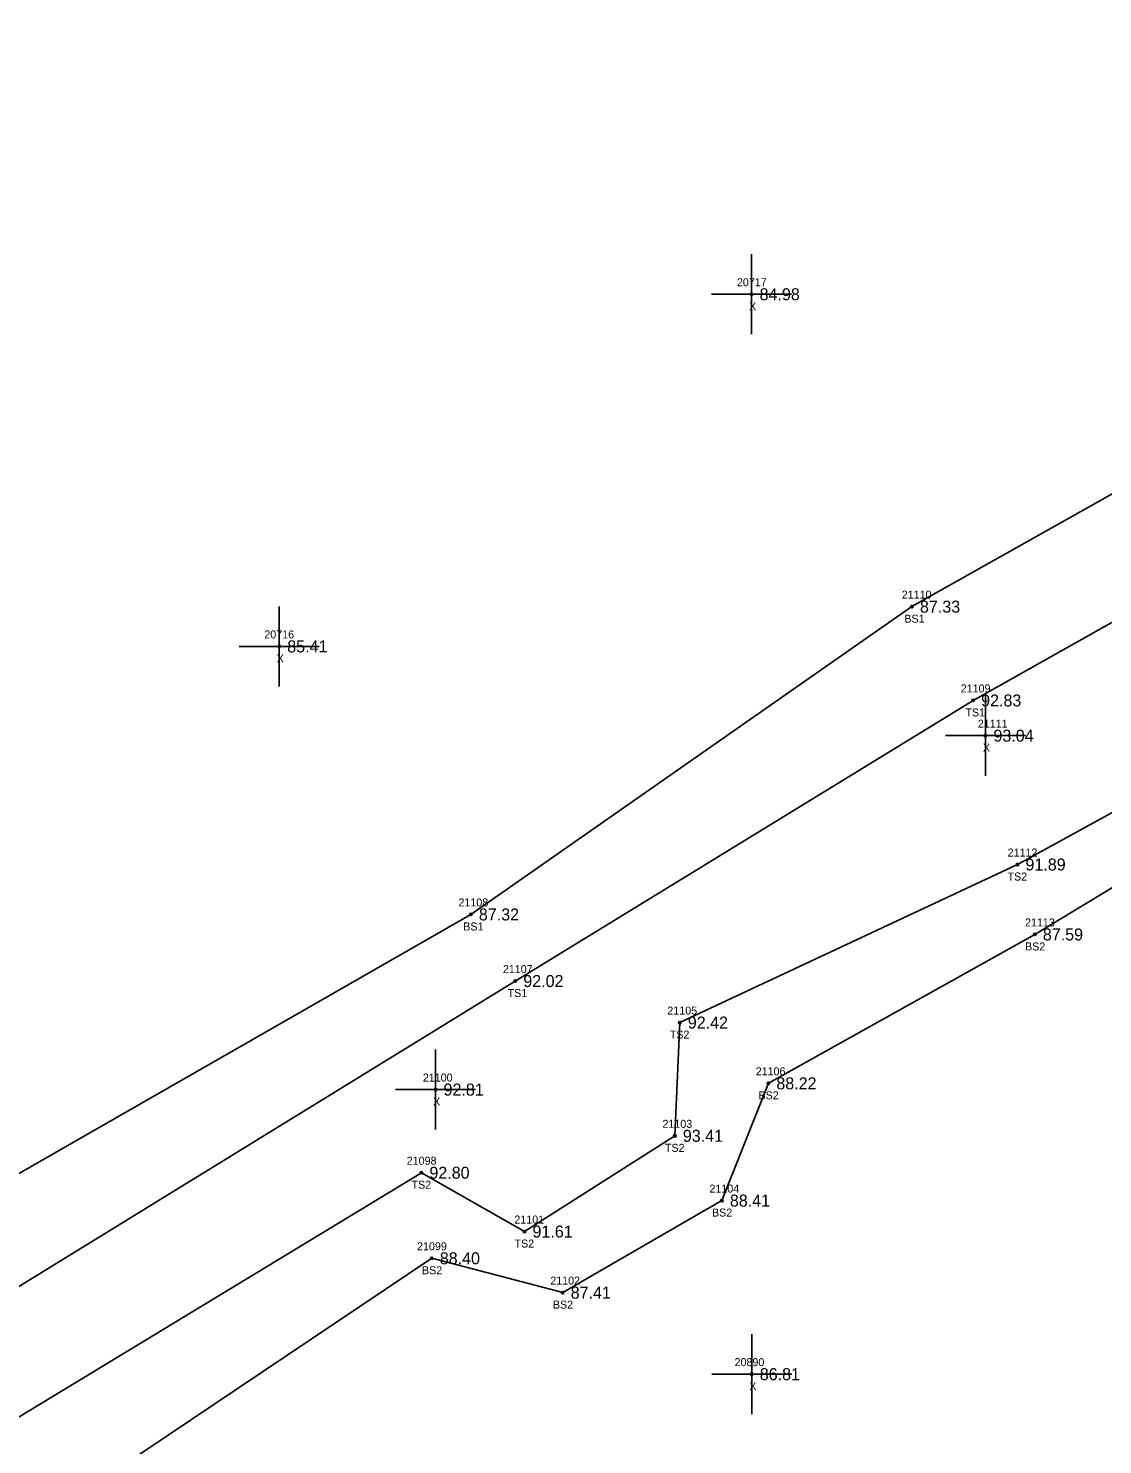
# Model space of a CAD drawing. Extents: x 2530197 to 2532051, y 935230 to 936631.
# Drawn here: x 2531258.3 to 2531392.5, y 936167.6 to 936344.6 of the extents above; entities that cross this region are included whole.
import ezdxf

# ---------------------------------------------------------------- set-up
doc = ezdxf.new("R2010")
doc.units = 0
for name, color, linetype in [('RD_DTM_BkLn2', 7, 'Continuous'), ('RD_DTM_BkLn_txCode', 7, 'Continuous'), ('RD_EX_Misc', 7, 'Continuous'), ('RD_EX_Misc_txCode', 7, 'Continuous'), ('RD_EX_TX_Misc_ELEV', 7, 'Continuous'), ('RD_SMD_Locator', 7, 'Continuous')]:
    doc.layers.add(name, color=color, linetype=linetype)

msp = doc.modelspace()

# ---------------------------------------------------------------- linework, layer by layer
at = {"layer": 'RD_DTM_BkLn2'}
for points in [[(2531151.41, 935999.3), (2531167.24, 936008.08), (2531181.24, 936018.79), (2531181.58, 936027.3), (2531178.12, 936073.45), (2531167.63, 936105.68), (2531166.35, 936111.09), (2531158.41, 936111.85), (2531152.62, 936122.31), (2531150.51, 936125.78), (2531152.42, 936137.74), (2531230.98, 936186.53), (2531313.57, 936233.84), (2531368.67, 936272.3), (2531431.6, 936307.72), (2531489.09, 936344.56)], [(2531153.52, 936135.49), (2531238.65, 936176.03), (2531319.12, 936225.52), (2531376.31, 936260.58), (2531439.07, 936295.88), (2531496.33, 936332.58)], [(2531229.61, 936049.23), (2531205.83, 936108.6), (2531204.82, 936125.4), (2531213.43, 936143.32), (2531245.76, 936164.18), (2531307.39, 936201.57), (2531320.27, 936194.22), (2531339.05, 936206.18), (2531339.67, 936220.33), (2531381.85, 936240.08), (2531451.4, 936278.23)], [(2531232.8, 936067.46), (2531215.52, 936108.97), (2531226.2, 936132.67), (2531251.54, 936152.54), (2531308.69, 936190.88), (2531325.04, 936186.59), (2531344.92, 936198.09), (2531350.73, 936212.74), (2531384.02, 936231.34), (2531448.45, 936270.32)]]:
    msp.add_lwpolyline(points, dxfattribs=at)
at = {"layer": 'RD_EX_Misc'}
for p, q in [((2531348.64, 936306.33), (2531348.64, 936316.33)), ((2531343.64, 936311.33), (2531353.64, 936311.33)), ((2531289.63, 936262.33), (2531289.63, 936272.33)), ((2531284.63, 936267.33), (2531294.63, 936267.33)), ((2531377.85, 936251.18), (2531377.85, 936261.18)), ((2531372.85, 936256.18), (2531382.85, 936256.18)), ((2531309.16, 936206.96), (2531309.16, 936216.96)), ((2531304.16, 936211.96), (2531314.16, 936211.96)), ((2531348.66, 936171.4), (2531348.66, 936181.4)), ((2531343.66, 936176.4), (2531353.66, 936176.4))]:
    msp.add_line(p, q, dxfattribs=at)
at = {"layer": 'RD_SMD_Locator'}
for centre in [(2531348.64, 936311.33), (2531368.67, 936272.3), (2531289.63, 936267.33), (2531376.31, 936260.58), (2531377.85, 936256.18), (2531381.85, 936240.08), (2531313.57, 936233.84), (2531384.02, 936231.34), (2531319.12, 936225.52), (2531339.67, 936220.33), (2531350.73, 936212.74), (2531309.16, 936211.96), (2531339.05, 936206.18), (2531307.39, 936201.57), (2531344.92, 936198.09), (2531320.27, 936194.22), (2531308.69, 936190.88), (2531325.04, 936186.59), (2531348.66, 936176.4)]:
    msp.add_circle(centre, 0.15, dxfattribs=at)

# ---------------------------------------------------------------- texts
at = {"layer": 'RD_DTM_BkLn_txCode'}
for s, p in [('21110', (2531367.4, 936273.3)), ('BS1', (2531367.72, 936270.3)), ('21109', (2531374.76, 936261.58)), ('TS1', (2531375.35, 936258.58)), ('21112', (2531380.62, 936241.08)), ('TS2', (2531380.61, 936238.08)), ('21108', (2531312.02, 936234.84)), ('BS1', (2531312.62, 936231.84)), ('21113', (2531382.79, 936232.34)), ('BS2', (2531382.79, 936229.34)), ('21107', (2531317.57, 936226.52)), ('TS1', (2531318.16, 936223.52)), ('21105', (2531338.11, 936221.33)), ('TS2', (2531338.42, 936218.33)), ('21106', (2531349.15, 936213.74)), ('BS2', (2531349.5, 936210.74)), ('21103', (2531337.5, 936207.18)), ('TS2', (2531337.81, 936204.18)), ('21098', (2531305.56, 936202.57)), ('TS2', (2531306.15, 936199.57)), ('21104', (2531343.37, 936199.09)), ('BS2', (2531343.69, 936196.09)), ('21101', (2531319, 936195.22)), ('21099', (2531306.85, 936191.88)), ('TS2', (2531319.02, 936192.22)), ('BS2', (2531307.46, 936188.88)), ('21102', (2531323.49, 936187.59)), ('BS2', (2531323.81, 936184.59))]:
    msp.add_text(s, height=1, dxfattribs=at).set_placement(p)
at = {"layer": 'RD_EX_Misc_txCode'}
for s, p in [('20717', (2531346.8, 936312.33)), ('X', (2531348.32, 936309.33)), ('20716', (2531287.77, 936268.33)), ('X', (2531289.32, 936265.33)), ('21111', (2531376.9, 936257.18)), ('X', (2531377.53, 936254.18)), ('21100', (2531307.57, 936212.96)), ('X', (2531308.85, 936209.96)), ('20890', (2531346.51, 936177.4)), ('X', (2531348.35, 936174.4))]:
    msp.add_text(s, height=1, dxfattribs=at).set_placement(p)
at = {"layer": 'RD_EX_TX_Misc_ELEV'}
for s, p in [('84.98', (2531349.64, 936310.58)), ('87.33', (2531369.67, 936271.55)), ('85.41', (2531290.63, 936266.58)), ('92.83', (2531377.31, 936259.83)), ('93.04', (2531378.85, 936255.43)), ('91.89', (2531382.85, 936239.33)), ('87.32', (2531314.57, 936233.09)), ('87.59', (2531385.02, 936230.59)), ('92.02', (2531320.12, 936224.77)), ('92.42', (2531340.67, 936219.58)), ('92.81', (2531310.16, 936211.21)), ('88.22', (2531351.73, 936211.99)), ('93.41', (2531340.05, 936205.43)), ('92.80', (2531308.39, 936200.82)), ('88.41', (2531345.92, 936197.34)), ('91.61', (2531321.27, 936193.47)), ('88.40', (2531309.69, 936190.13)), ('87.41', (2531326.04, 936185.84)), ('86.81', (2531349.66, 936175.65))]:
    msp.add_text(s, height=1.5, dxfattribs=at).set_placement(p)

doc.saveas('drawing.dxf')
